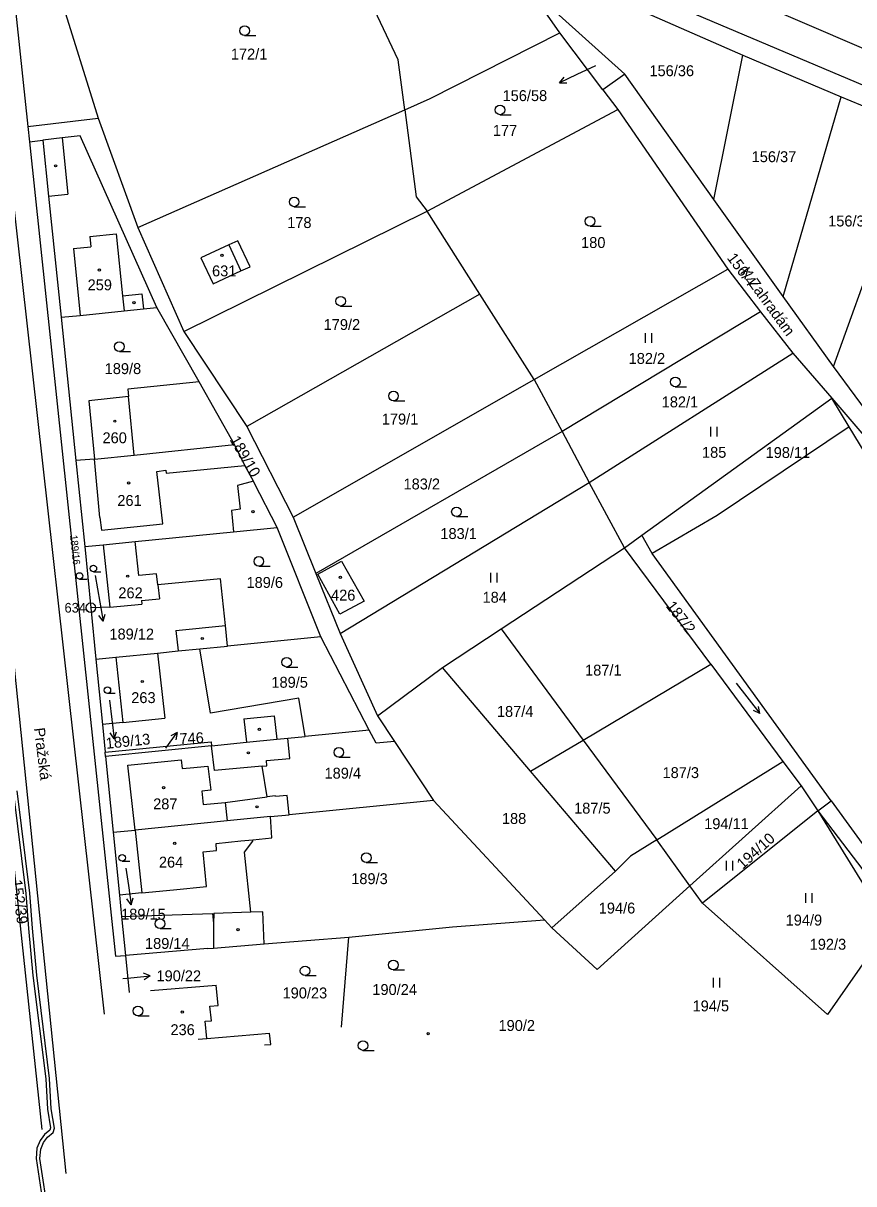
# Model space of a CAD drawing. Extents: x -783948 to -781889, y -1005870 to -1004430.
# Drawn here: x -782917.3 to -782787.9, y -1005271.1 to -1005090.2 of the extents above; entities that cross this region are included whole.
import ezdxf

# ---------------------------------------------------------------- set-up
doc = ezdxf.new("R2010")
doc.units = 0
for name, color, linetype in [('Vrstva 1', 7, 'Continuous'), ('Vrstva 13', 7, 'Continuous'), ('Vrstva 2', 7, 'Continuous'), ('Vrstva 3', 7, 'Continuous'), ('Vrstva 4', 7, 'Continuous'), ('Vrstva 5', 7, 'Continuous'), ('Vrstva 6', 7, 'Continuous'), ('Vrstva 7', 7, 'Continuous'), ('Vrstva 8', 7, 'Continuous')]:
    doc.layers.add(name, color=color, linetype=linetype)

msp = doc.modelspace()

# ---------------------------------------------------------------- linework, layer by layer
at = {"layer": 'Vrstva 1'}
for p, q in [((-782922.29, -1005051.97), (-782916.56, -1005106.32)), ((-782913.56, -1005079.53), (-782905.62, -1005105.04)), ((-782834.19, -1005082.44), (-782805.15, -1005095.21)), ((-782838.68, -1005084.56), (-782823.51, -1005098.16)), ((-782833.65, -1005091.74), (-782838.68, -1005084.56)), ((-782826.94, -1005100.61), (-782833.65, -1005091.74)), ((-782809.69, -1005117.73), (-782805.15, -1005095.21)), ((-782805.15, -1005095.21), (-782789.82, -1005101.7)), ((-782823.51, -1005098.16), (-782826.94, -1005100.61)), ((-782809.69, -1005117.73), (-782823.51, -1005098.16)), ((-782826.94, -1005100.61), (-782824.64, -1005103.66)), ((-782798.84, -1005132.84), (-782789.82, -1005101.7)), ((-782789.82, -1005101.7), (-782777.73, -1005106.76)), ((-782899.42, -1005122.06), (-782857.83, -1005103.75)), ((-782854.36, -1005119.53), (-782824.64, -1005103.66)), ((-782824.64, -1005103.66), (-782807.46, -1005128.58)), ((-782916.56, -1005106.32), (-782905.62, -1005105.04)), ((-782916.56, -1005106.32), (-782916.31, -1005108.71)), ((-782905.62, -1005105.04), (-782899.42, -1005122.06)), ((-782791.04, -1005143.73), (-782777.73, -1005106.76)), ((-782916.31, -1005108.71), (-782914.22, -1005108.47)), ((-782916.31, -1005108.71), (-782902.92, -1005235.66)), ((-782914.35, -1005262.66), (-782930.61, -1005111.11)), ((-782798.84, -1005132.84), (-782809.69, -1005117.73)), ((-782892.27, -1005138.26), (-782854.36, -1005119.53)), ((-782846.13, -1005132.47), (-782854.36, -1005119.53)), ((-782899.42, -1005122.06), (-782892.27, -1005138.26)), ((-782837.66, -1005145.79), (-782807.46, -1005128.58)), ((-782807.46, -1005128.58), (-782802.38, -1005135.2)), ((-782846.13, -1005132.47), (-782882.45, -1005153.08)), ((-782837.66, -1005145.79), (-782846.13, -1005132.47)), ((-782791.04, -1005143.73), (-782798.84, -1005132.84)), ((-782889.88, -1005146.12), (-782896.44, -1005134.54)), ((-782802.38, -1005135.2), (-782833.31, -1005153.89)), ((-782802.38, -1005135.2), (-782797.38, -1005141.66)), ((-782911.39, -1005136.07), (-782909.07, -1005158.4)), ((-782892.27, -1005138.26), (-782882.45, -1005153.08)), ((-782829.1, -1005161.82), (-782797.38, -1005141.66)), ((-782797.38, -1005141.66), (-782791.29, -1005148.67)), ((-782784.29, -1005152.86), (-782791.04, -1005143.73)), ((-782884.34, -1005155.9), (-782889.88, -1005146.12)), ((-782875.23, -1005167.21), (-782837.66, -1005145.79)), ((-782837.66, -1005145.79), (-782833.31, -1005153.89)), ((-782820.89, -1005170.05), (-782791.29, -1005148.67)), ((-782791.29, -1005148.67), (-782768.37, -1005175.51)), ((-782788.58, -1005153.12), (-782791.29, -1005148.67)), ((-782882.45, -1005153.08), (-782875.23, -1005167.21)), ((-782833.31, -1005153.89), (-782871.67, -1005176)), ((-782833.31, -1005153.89), (-782829.1, -1005161.82)), ((-782906.19, -1005158.2), (-782909.07, -1005158.4)), ((-782909.07, -1005158.4), (-782907.68, -1005171.8)), ((-782867.87, -1005185.36), (-782829.1, -1005161.82)), ((-782823.58, -1005171.99), (-782829.1, -1005161.82)), ((-782875.23, -1005167.21), (-782871.67, -1005176)), ((-782870.89, -1005185.87), (-782877.71, -1005168.81)), ((-782823.58, -1005171.99), (-782820.89, -1005170.05)), ((-782819.26, -1005172.91), (-782820.89, -1005170.05)), ((-782907.68, -1005171.8), (-782904.83, -1005171.51)), ((-782907.68, -1005171.8), (-782906.76, -1005181.34)), ((-782904.83, -1005171.51), (-782899.84, -1005171.02)), ((-782842.83, -1005184.65), (-782823.58, -1005171.99)), ((-782810.14, -1005190.13), (-782823.58, -1005171.99)), ((-782791.38, -1005211.44), (-782819.26, -1005172.91)), ((-782871.67, -1005176), (-782867.87, -1005185.36)), ((-782906.76, -1005181.34), (-782905.96, -1005189.36)), ((-782870.89, -1005185.87), (-782885.43, -1005187.31)), ((-782863.35, -1005200.41), (-782870.89, -1005185.87)), ((-782867.87, -1005185.36), (-782862.1, -1005198.17)), ((-782851.96, -1005190.66), (-782842.83, -1005184.65)), ((-782842.83, -1005184.65), (-782830.04, -1005201.97)), ((-782889.77, -1005187.74), (-782885.43, -1005187.31)), ((-782905.96, -1005189.36), (-782902.87, -1005189.05)), ((-782905.96, -1005189.36), (-782904.95, -1005199.53)), ((-782862.1, -1005198.17), (-782851.96, -1005190.66)), ((-782838.21, -1005206.83), (-782851.96, -1005190.66)), ((-782830.04, -1005201.97), (-782810.14, -1005190.13)), ((-782810.14, -1005190.13), (-782798.89, -1005205.31)), ((-782862.1, -1005198.17), (-782859.44, -1005202.19)), ((-782904.95, -1005199.53), (-782904.52, -1005203.87)), ((-782863.35, -1005200.41), (-782873.35, -1005201.4)), ((-782904.52, -1005203.87), (-782887.99, -1005202.23)), ((-782887.99, -1005202.23), (-782887.92, -1005202.85)), ((-782876.03, -1005201.67), (-782873.35, -1005201.4)), ((-782859.44, -1005202.19), (-782853.37, -1005211.36)), ((-782838.21, -1005206.83), (-782830.04, -1005201.97)), ((-782830.04, -1005201.97), (-782818.55, -1005217.54)), ((-782904.46, -1005204.5), (-782904.52, -1005203.87)), ((-782887.92, -1005202.85), (-782904.46, -1005204.5)), ((-782904.46, -1005204.5), (-782903.28, -1005216.33)), ((-782818.55, -1005217.54), (-782798.89, -1005205.31)), ((-782798.89, -1005205.31), (-782796.08, -1005209.1)), ((-782824.98, -1005222.39), (-782838.21, -1005206.83)), ((-782796.08, -1005209.1), (-782813.38, -1005224.71)), ((-782796.08, -1005209.1), (-782793.47, -1005212.99)), ((-782853.37, -1005211.36), (-782875.83, -1005213.6)), ((-782853.37, -1005211.36), (-782836.04, -1005230)), ((-782793.47, -1005212.99), (-782791.38, -1005211.44)), ((-782791.38, -1005211.44), (-782779.76, -1005227.49)), ((-782793.47, -1005212.99), (-782811.43, -1005227.4)), ((-782793.47, -1005212.99), (-782782.38, -1005230.97)), ((-782878.75, -1005213.89), (-782875.83, -1005213.6)), ((-782903.28, -1005216.33), (-782899.86, -1005215.99)), ((-782903.28, -1005216.33), (-782902.3, -1005226.15)), ((-782813.38, -1005224.71), (-782818.55, -1005217.54)), ((-782834.89, -1005231.24), (-782824.98, -1005222.39)), ((-782902.3, -1005226.15), (-782901.97, -1005229.46)), ((-782813.38, -1005224.71), (-782827.83, -1005237.75)), ((-782811.43, -1005227.4), (-782813.38, -1005224.71)), ((-782791.93, -1005244.74), (-782811.43, -1005227.4)), ((-782901.97, -1005229.46), (-782901.37, -1005235.53)), ((-782866.54, -1005232.66), (-782850.37, -1005231.07)), ((-782850.37, -1005231.07), (-782836.04, -1005230)), ((-782836.04, -1005230), (-782834.89, -1005231.24)), ((-782827.83, -1005237.75), (-782834.89, -1005231.24)), ((-782782.38, -1005230.97), (-782791.93, -1005244.74)), ((-782879.76, -1005233.75), (-782866.54, -1005232.66)), ((-782867.68, -1005246.73), (-782866.54, -1005232.66)), ((-782888.54, -1005234.47), (-782901.37, -1005235.53)), ((-782888.54, -1005234.47), (-782887.64, -1005234.4)), ((-782887.64, -1005234.4), (-782879.76, -1005233.75)), ((-782902.92, -1005235.66), (-782901.37, -1005235.53)), ((-782901.37, -1005235.53), (-782900.8, -1005241.29))]:
    msp.add_line(p, q, dxfattribs=at)
for points in [[(-782603.34, -1005170.09), (-782670.21, -1005142.63), (-782705.63, -1005128.88), (-782803.2, -1005086.94), (-782810.41, -1005084.95), (-782850.5, -1005065.89)], [(-782857.83, -1005103.75), (-782858.86, -1005095.96), (-782871.73, -1005068.67)], [(-782857.83, -1005103.75), (-782853.88, -1005101.95), (-782833.65, -1005091.74)], [(-782857.83, -1005103.75), (-782856.05, -1005117.28), (-782854.36, -1005119.53)], [(-782896.44, -1005134.54), (-782908.41, -1005107.79), (-782911.23, -1005108.12), (-782914.22, -1005108.47)], [(-782914.22, -1005108.47), (-782913.32, -1005117.21), (-782911.39, -1005136.07)], [(-782883.83, -1005124.13), (-782885.25, -1005124.79), (-782889.59, -1005126.82), (-782887.71, -1005130.87), (-782883.36, -1005128.84), (-782881.94, -1005128.18), (-782883.83, -1005124.13)], [(-782911.39, -1005136.07), (-782908.39, -1005135.77), (-782901.55, -1005135.07), (-782898.55, -1005134.76), (-782896.44, -1005134.54)], [(-782889.88, -1005146.12), (-782900.98, -1005147.29), (-782900.87, -1005148.42), (-782907.06, -1005149.07), (-782906.19, -1005158.2)], [(-782788.58, -1005153.12), (-782809.14, -1005166.97), (-782819.26, -1005172.91)], [(-782759.14, -1005186.33), (-782765.98, -1005181.44), (-782776.41, -1005173.12), (-782788.58, -1005153.12)], [(-782906.19, -1005158.2), (-782900, -1005157.55), (-782884.34, -1005155.9)], [(-782877.71, -1005168.81), (-782881.27, -1005161.89), (-782881.42, -1005161.62), (-782882.76, -1005159.15), (-782884.34, -1005155.9)], [(-782899.84, -1005171.02), (-782884.54, -1005169.49), (-782877.71, -1005168.81)], [(-782904.83, -1005171.51), (-782903.77, -1005181.25), (-782906.76, -1005181.34)], [(-782885.43, -1005187.31), (-782885.77, -1005184.13), (-782886.56, -1005176.82), (-782896.3, -1005177.79), (-782896.49, -1005176.03), (-782899.27, -1005176.3), (-782899.84, -1005171.02)], [(-782871.35, -1005176.09), (-782867.67, -1005174.1), (-782864.17, -1005180.3), (-782867.96, -1005182.35), (-782871.35, -1005176.09)], [(-782902.87, -1005189.05), (-782896.34, -1005188.4), (-782893.14, -1005188.08), (-782889.77, -1005187.74)], [(-782873.35, -1005201.4), (-782874.34, -1005195.43), (-782888.11, -1005197.76), (-782889.77, -1005187.74)], [(-782902.87, -1005189.05), (-782901.77, -1005199.21), (-782904.95, -1005199.53)], [(-782859.44, -1005202.19), (-782862.28, -1005202.47), (-782863.35, -1005200.41)], [(-782887.92, -1005202.85), (-782882.49, -1005202.31), (-782877.78, -1005201.84), (-782876.03, -1005201.67)], [(-782879.33, -1005205.98), (-782879.38, -1005205.15), (-782875.76, -1005204.84), (-782876.03, -1005201.67)], [(-782878.01, -1005210.66), (-782879.26, -1005210.82), (-782880.05, -1005206.05), (-782879.33, -1005205.98)], [(-782875.83, -1005213.6), (-782876.14, -1005210.61), (-782877.97, -1005210.77), (-782878.01, -1005210.66)], [(-782793.47, -1005212.99), (-782780.29, -1005230.31), (-782772.95, -1005241.45)], [(-782878.75, -1005213.89), (-782885.52, -1005214.56), (-782899.86, -1005215.99)], [(-782879.76, -1005233.75), (-782879.93, -1005228.72), (-782881.8, -1005228.78), (-782882.82, -1005219.42), (-782881.48, -1005217.72), (-782881.5, -1005217.5), (-782878.53, -1005217.2), (-782878.75, -1005213.89)], [(-782899.86, -1005215.99), (-782898.8, -1005225.8), (-782902.3, -1005226.15)], [(-782818.55, -1005217.54), (-782822.64, -1005220.08), (-782824.98, -1005222.39)], [(-782901.97, -1005229.46), (-782887.78, -1005228.99), (-782887.61, -1005230.55), (-782887.64, -1005234.4)]]:
    msp.add_lwpolyline(points, dxfattribs=at)
at = {"layer": 'Vrstva 13'}
for points in [[(-782913.29, -1005276.32), (-782914.67, -1005267.18), (-782914.55, -1005265.73), (-782914.13, -1005264.68), (-782913.51, -1005263.87), (-782912.6, -1005263.13), (-782912.4, -1005262.43), (-782912.91, -1005259.43), (-782913.17, -1005254.72), (-782915.16, -1005238.61), (-782915.85, -1005231.27), (-782916.26, -1005225.81), (-782918.24, -1005209.87)], [(-782918.84, -1005209.93), (-782916.86, -1005225.87), (-782916.45, -1005231.33), (-782915.76, -1005238.67), (-782913.77, -1005254.78), (-782913.51, -1005259.49), (-782913.02, -1005262.39), (-782913.12, -1005262.79), (-782913.95, -1005263.45), (-782914.22, -1005263.83), (-782914.63, -1005264.38), (-782915.15, -1005265.59), (-782915.27, -1005267.2), (-782913.87, -1005276.54)]]:
    msp.add_lwpolyline(points, dxfattribs=at)
at = {"layer": 'Vrstva 3'}
for p, q in [((-782882.78, -1005092.15), (-782881.03, -1005092.15)), ((-782842.98, -1005104.49), (-782841.23, -1005104.49)), ((-782875.06, -1005118.83), (-782873.31, -1005118.83)), ((-782828.96, -1005121.86), (-782827.21, -1005121.86)), ((-782867.82, -1005134.31), (-782866.07, -1005134.31)), ((-782820.32, -1005140.04), (-782820.32, -1005138.54)), ((-782819.32, -1005140.04), (-782819.32, -1005138.54)), ((-782902.3, -1005141.39), (-782900.55, -1005141.39)), ((-782815.67, -1005146.89), (-782813.92, -1005146.89)), ((-782859.58, -1005149.08), (-782857.83, -1005149.08)), ((-782810.14, -1005154.66), (-782810.14, -1005153.16)), ((-782809.14, -1005154.66), (-782809.14, -1005153.16)), ((-782849.77, -1005167.14), (-782848.02, -1005167.14)), ((-782880.57, -1005174.86), (-782878.82, -1005174.86)), ((-782908.49, -1005176.88), (-782907.32, -1005176.88)), ((-782906.34, -1005175.73), (-782905.17, -1005175.73)), ((-782844.43, -1005177.39), (-782844.43, -1005175.89)), ((-782843.43, -1005177.39), (-782843.43, -1005175.89)), ((-782876.24, -1005190.58), (-782874.49, -1005190.58)), ((-782806.2, -1005193.08), (-782802.51, -1005197.8)), ((-782904.16, -1005194.68), (-782902.98, -1005194.68)), ((-782802.51, -1005197.8), (-782802.72, -1005196.72)), ((-782802.51, -1005197.8), (-782803.51, -1005197.34)), ((-782868.1, -1005204.63), (-782866.35, -1005204.63)), ((-782901.85, -1005220.82), (-782900.68, -1005220.82)), ((-782863.82, -1005221.05), (-782862.07, -1005221.05)), ((-782807.71, -1005222.28), (-782807.71, -1005220.78)), ((-782806.71, -1005222.28), (-782806.71, -1005220.78)), ((-782795.34, -1005227.33), (-782795.34, -1005225.83)), ((-782794.34, -1005227.33), (-782794.34, -1005225.83)), ((-782895.96, -1005231.34), (-782894.21, -1005231.34)), ((-782873.36, -1005238.68), (-782871.61, -1005238.68)), ((-782859.61, -1005237.77), (-782857.86, -1005237.77)), ((-782809.72, -1005240.54), (-782809.72, -1005239.04)), ((-782808.72, -1005240.54), (-782808.72, -1005239.04)), ((-782899.4, -1005244.94), (-782897.65, -1005244.94)), ((-782864.34, -1005250.33), (-782862.59, -1005250.33))]:
    msp.add_line(p, q, dxfattribs=at)
for centre, radius in [((-782882.78, -1005091.4), 0.75), ((-782842.98, -1005103.74), 0.75), ((-782875.06, -1005118.08), 0.75), ((-782828.96, -1005121.11), 0.75), ((-782867.82, -1005133.56), 0.75), ((-782902.3, -1005140.64), 0.75), ((-782815.67, -1005146.14), 0.75), ((-782859.58, -1005148.33), 0.75), ((-782849.77, -1005166.39), 0.75), ((-782880.57, -1005174.11), 0.75), ((-782906.35, -1005175.23), 0.502), ((-782908.5, -1005176.38), 0.502), ((-782876.24, -1005189.83), 0.75), ((-782904.16, -1005194.18), 0.502), ((-782868.1, -1005203.88), 0.75), ((-782901.86, -1005220.32), 0.502), ((-782863.82, -1005220.3), 0.75), ((-782895.96, -1005230.59), 0.75), ((-782859.61, -1005237.02), 0.75), ((-782873.36, -1005237.93), 0.75), ((-782899.4, -1005244.19), 0.75), ((-782864.34, -1005249.58), 0.75)]:
    msp.add_circle(centre, radius, dxfattribs=at)
at = {"layer": 'Vrstva 4'}
for p, q in [((-782911.23, -1005108.12), (-782910.32, -1005116.9)), ((-782919.91, -1005108.66), (-782904.65, -1005244.68)), ((-782913.32, -1005117.21), (-782910.32, -1005116.9)), ((-782906.92, -1005123.5), (-782902.78, -1005123.07)), ((-782906.92, -1005123.5), (-782906.76, -1005125.08)), ((-782902.78, -1005123.07), (-782901.79, -1005132.7)), ((-782885.25, -1005124.79), (-782883.36, -1005128.84)), ((-782909.45, -1005125.36), (-782906.76, -1005125.08)), ((-782909.45, -1005125.36), (-782908.39, -1005135.77)), ((-782901.79, -1005132.7), (-782898.79, -1005132.39)), ((-782901.79, -1005132.7), (-782901.55, -1005135.07)), ((-782898.79, -1005132.39), (-782898.55, -1005134.76)), ((-782900, -1005157.55), (-782900.87, -1005148.42)), ((-782905.33, -1005167.25), (-782906.19, -1005158.2)), ((-782921.8, -1005160.42), (-782910.66, -1005269.54)), ((-782896.3, -1005177.79), (-782896.07, -1005179.93)), ((-782903.77, -1005181.25), (-782898.78, -1005180.76)), ((-782898.84, -1005180.2), (-782896.07, -1005179.93)), ((-782898.84, -1005180.2), (-782898.78, -1005180.76)), ((-782893.49, -1005184.9), (-782885.77, -1005184.13)), ((-782893.49, -1005184.9), (-782893.14, -1005188.08)), ((-782896.34, -1005188.4), (-782895.24, -1005198.56)), ((-782901.77, -1005199.21), (-782895.24, -1005198.56)), ((-782882.88, -1005198.68), (-782878.17, -1005198.21)), ((-782882.88, -1005198.68), (-782882.49, -1005202.31)), ((-782878.17, -1005198.21), (-782877.78, -1005201.84)), ((-782887.48, -1005206.73), (-782887.92, -1005202.85)), ((-782900.96, -1005205.89), (-782892.69, -1005205.07)), ((-782899.86, -1005215.99), (-782900.96, -1005205.89)), ((-782892.69, -1005205.07), (-782892.54, -1005206.42)), ((-782891.26, -1005206.29), (-782888.5, -1005206.01)), ((-782888.5, -1005206.01), (-782888.05, -1005209.78)), ((-782880.05, -1005206.05), (-782887.48, -1005206.73)), ((-782892.54, -1005206.42), (-782891.26, -1005206.29)), ((-782888.05, -1005209.78), (-782889.46, -1005209.92)), ((-782889.46, -1005209.92), (-782889.23, -1005212.02)), ((-782889.23, -1005212.02), (-782885.83, -1005211.68)), ((-782885.83, -1005211.68), (-782879.26, -1005210.82)), ((-782885.83, -1005211.68), (-782885.52, -1005214.56)), ((-782887.24, -1005218.1), (-782883.38, -1005217.69)), ((-782887.17, -1005219.16), (-782887.24, -1005218.1)), ((-782883.38, -1005217.69), (-782881.5, -1005217.5)), ((-782889.22, -1005219.4), (-782887.17, -1005219.16)), ((-782888.73, -1005224.79), (-782889.22, -1005219.4)), ((-782898.8, -1005225.8), (-782893.89, -1005225.31)), ((-782893.89, -1005225.31), (-782888.73, -1005224.79)), ((-782887.6, -1005228.98), (-782887.61, -1005230.55)), ((-782881.8, -1005228.78), (-782887.6, -1005228.98)), ((-782897.44, -1005241.01), (-782887.23, -1005240.16)), ((-782886.89, -1005243.33), (-782887.23, -1005240.16)), ((-782888.21, -1005243.44), (-782886.89, -1005243.33)), ((-782887.97, -1005245.71), (-782888.21, -1005243.44)), ((-782888.94, -1005245.79), (-782887.97, -1005245.71)), ((-782888.66, -1005248.46), (-782888.94, -1005245.79)), ((-782888.66, -1005248.46), (-782878.89, -1005247.64)), ((-782878.7, -1005249.4), (-782878.89, -1005247.64)), ((-782890.02, -1005248.57), (-782888.66, -1005248.46)), ((-782879.66, -1005249.48), (-782878.7, -1005249.4))]:
    msp.add_line(p, q, dxfattribs=at)
for points in [[(-782905.33, -1005167.25), (-782905.07, -1005169.25), (-782895.55, -1005168.28), (-782896.46, -1005160.09), (-782895.08, -1005159.91), (-782895.01, -1005160.38), (-782882.76, -1005159.15)], [(-782881.42, -1005161.62), (-782883.89, -1005162.27), (-782883.47, -1005166), (-782884.82, -1005166.16), (-782884.54, -1005169.49)]]:
    msp.add_lwpolyline(points, dxfattribs=at)
at = {"layer": 'Vrstva 5'}
for centre in [(-782912.23, -1005112.46), (-782886.31, -1005126.4), (-782905.41, -1005128.7), (-782900.04, -1005133.79), (-782903.01, -1005152.26), (-782900.86, -1005161.88), (-782881.48, -1005166.35), (-782900.99, -1005176.42), (-782867.85, -1005176.61), (-782889.38, -1005186.13), (-782898.74, -1005192.83), (-782880.48, -1005200.29), (-782882.19, -1005203.96), (-782895.4, -1005209.37), (-782880.85, -1005212.37), (-782893.68, -1005218.06), (-782883.8, -1005231.52), (-782892.5, -1005244.36), (-782854.18, -1005247.74)]:
    msp.add_circle(centre, 0.175, dxfattribs=at)
at = {"layer": 'Vrstva 6'}
msp.add_line((-782841.72, -1005076.44), (-782641.6, -1005161.34), dxfattribs=at)
at = {"layer": 'Vrstva 7'}
for p, q in [((-782828.13, -1005096.88), (-782830.99, -1005098.24)), ((-782830.99, -1005098.24), (-782833.71, -1005099.51)), ((-782833.71, -1005099.51), (-782833.01, -1005098.63)), ((-782833.71, -1005099.51), (-782832.59, -1005099.54)), ((-782906.05, -1005176.3), (-782905.35, -1005180.48)), ((-782905.35, -1005180.48), (-782904.83, -1005183.44)), ((-782904.83, -1005183.44), (-782905.5, -1005182.54)), ((-782904.83, -1005183.44), (-782904.51, -1005182.36)), ((-782903.86, -1005195.73), (-782903.5, -1005198.78)), ((-782903.5, -1005198.78), (-782903.13, -1005201.76)), ((-782903.13, -1005201.76), (-782903.75, -1005200.83)), ((-782903.13, -1005201.76), (-782902.76, -1005200.7)), ((-782895.08, -1005203.21), (-782893.27, -1005200.81)), ((-782893.27, -1005200.81), (-782894.28, -1005201.31)), ((-782893.27, -1005200.81), (-782893.48, -1005201.91)), ((-782901.27, -1005221.94), (-782900.9, -1005224.65)), ((-782900.9, -1005224.65), (-782900.48, -1005227.62)), ((-782900.48, -1005227.62), (-782901.12, -1005226.7)), ((-782900.48, -1005227.62), (-782900.13, -1005226.56)), ((-782900.5, -1005239.02), (-782897.52, -1005238.71)), ((-782897.52, -1005238.71), (-782898.56, -1005238.31)), ((-782897.52, -1005238.71), (-782898.46, -1005239.31)), ((-782901.78, -1005239.15), (-782900.5, -1005239.02))]:
    msp.add_line(p, q, dxfattribs=at)
at = {"layer": 'Vrstva 8'}
for radius in [0.75, 0.03]:
    msp.add_circle((-782906.75, -1005181.34), radius, dxfattribs=at)

# ---------------------------------------------------------------- texts
at = {"layer": 'Vrstva 2'}
for s, p in [('172/1', (-782884.93, -1005095.89)), ('156/36', (-782819.7, -1005098.49)), ('156/58', (-782842.59, -1005102.37)), ('177', (-782844.1, -1005107.79)), ('156/37', (-782803.77, -1005111.89)), ('178', (-782876.15, -1005122.16)), ('156/38', (-782791.85, -1005121.91)), ('180', (-782830.35, -1005125.27)), ('631', (-782887.86, -1005129.69)), ('259', (-782907.25, -1005131.86)), ('179/2', (-782870.47, -1005138.05)), ('182/2', (-782822.94, -1005143.33)), ('189/8', (-782904.59, -1005144.92)), ('182/1', (-782817.79, -1005150.11)), ('179/1', (-782861.41, -1005152.78)), ('260', (-782904.93, -1005155.7)), ('185', (-782811.51, -1005157.97)), ('198/11', (-782801.6, -1005158)), ('183/2', (-782858.02, -1005162.9)), ('261', (-782902.62, -1005165.47)), ('183/1', (-782852.28, -1005170.63)), ('189/6', (-782882.49, -1005178.25)), ('262', (-782902.46, -1005179.87)), ('426', (-782869.32, -1005180.23)), ('184', (-782845.71, -1005180.56)), ('189/12', (-782903.85, -1005186.29)), ('187/1', (-782829.73, -1005191.92)), ('189/5', (-782878.61, -1005193.81)), ('263', (-782900.45, -1005196.2)), ('187/4', (-782843.47, -1005198.35)), ('189/4', (-782870.33, -1005207.98)), ('187/3', (-782817.66, -1005207.89)), ('287', (-782897.04, -1005212.76)), ('187/5', (-782831.44, -1005213.43)), ('188', (-782842.69, -1005215.04)), ('194/11', (-782811.17, -1005215.85)), ('264', (-782896.14, -1005221.84)), ('189/3', (-782866.17, -1005224.42)), ('194/6', (-782827.6, -1005229)), ('189/15', (-782902.03, -1005229.95)), ('194/9', (-782798.48, -1005230.87)), ('189/14', (-782898.31, -1005234.52)), ('192/3', (-782794.73, -1005234.64)), ('190/22', (-782896.52, -1005239.56)), ('190/23', (-782876.87, -1005242.23)), ('190/24', (-782862.88, -1005241.7)), ('194/5', (-782812.98, -1005244.25)), ('190/2', (-782843.22, -1005247.3)), ('236', (-782894.34, -1005247.96))]:
    msp.add_text(s, height=1.7, dxfattribs=at).set_placement(p)
for s, height, rotation, p in [('156/4', 1.7, 307, (-782807.7, -1005126.84)), ('189/10', 1.7, 300, (-782885.16, -1005155.14)), ('189/16', 1.14, 276, (-782909.99, -1005170.06)), ('187/2', 1.7, 308, (-782817.22, -1005181.11)), ('746', 1.7, 3, (-782892.89, -1005202.62)), ('189/13', 1.7, 6, (-782904.33, -1005203.34)), ('194/10', 1.7, 42, (-782805.16, -1005222.18)), ('152/39', 1.7, 278, (-782919.17, -1005223.85))]:
    msp.add_text(s, height=height, rotation=rotation, dxfattribs=at).set_placement(p)
at = {"layer": 'Vrstva 7'}
for s, rotation, p in [('K Zahradám', 306, (-782805.63, -1005129.04)), ('Pražská', 277, (-782915.61, -1005200.13))]:
    msp.add_text(s, height=1.7, rotation=rotation, dxfattribs=at).set_placement(p)
at = {"layer": 'Vrstva 8'}
msp.add_text('634', height=1.5, dxfattribs=at).set_placement((-782910.85, -1005182.09))

doc.saveas('drawing.dxf')
